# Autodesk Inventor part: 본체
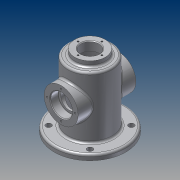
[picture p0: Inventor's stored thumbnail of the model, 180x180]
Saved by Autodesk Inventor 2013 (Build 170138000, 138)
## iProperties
Created: 2014-12
Part Number: 본체
Material: 알루미늄 6061
Document SubType Name: Modeling
Designer: CAD-B13
Mass: 479.555 g
Surface Area: 607.361 cm^2
Volume: 176.958 cm^3
Density: 2.71 g/cm^3
Author: CAD-B13
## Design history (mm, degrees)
sketch "스케치1"
  geometry: L1 (0, 106)-(0, 0); L2 (0, 106)-(22.5, 106); L3 (22.5, 106)-(22.5, 98); L4 (22.5, 98)-(32.5, 98); L5 (32.5, 98)-(32.5, 8); L6 (32.5, 8)-(52.5, 8); L7 (52.5, 8)-(52.5, 0); L8 (52.5, 0)-(0, 0); L9 (13.5, 106)-(13.5, 93); L10 (13.5, 93)-(27.5, 93); L11 (27.5, 93)-(27.5, 0); 1 further point
  constraints: 22 end point, 5 parallel, 5 perpendicular, 2 point on line, 1 coincident, 1 vertical
  dimensions: "d0" = 106 distance of L1.start L1.end; "d2" = 8 distance between parallel lines of L8 L6; "d3" = 45 diameter of L3 L1; "d4" = 65 diameter of L5 L1; "d5" = 98 distance between parallel lines of L8 L4; "d6" = 105 diameter of L7 L1; "d7" = 27 diameter of L9 L1; "d8" = 55 diameter of L11 L1; "d9" = 93 distance between parallel lines of L8 L10
revolve "회전1" sketch "스케치1" stored, may be unused: angle "d10" = 90 deg
node "작업 평면1"
sketch "스케치2"
  geometry: L1 (0, 52.5)-(0, -52.5) reference; C1 r 25 at (55, 0); 2 further points
  constraints: 1 centre point, 1 horizontal alignment, 1 midpoint
  dimensions: "d12" = 55 distance from line of L1 C1.centre; "d13" = 50 diameter of C1
extrude "돌출1" join sketch "스케치2" stored distance "d14" = 10; taper "d15" = 0 deg
hole "구멍1" diameter "d18" = 25; stored, may be unused: countersink angle "d22" = 90 deg, drill point angle "d24" = 0 deg; dims "d16" = 10, "d17" = 10, "d19" = 6, "d20" = 32, "d21" = 12, "d23" = 30.25
sketch "스케치3"
  geometry: C1 r 12.5 at (0, 0) reference; 2 further points
  constraints: 1 vertical alignment
  dimensions: "d25" = 20.5 distance of C1.centre point (0, 20.5)
hole "구멍2" sketch "스케치3" at (0, 20.5) diameter "d26" = 2.459; stored, may be unused: countersink angle "d30" = 90 deg, drill point angle "d32" = 118 deg; dims "d27" = 6, "d28" = 32, "d29" = 12, "d31" = 8
sketch "스케치4" dims "d36" = 86
  geometry: L1 (0, 0)-(30.406, 30.406); L2 (0, 0)-(43, 0); 2 further points
  constraints: 4 end point, 2 coincident, 1 equal length, 1 horizontal, 3 other
  dimensions: "d37" = 45 deg angle of L2 L1
hole "구멍3" sketch "스케치4" at (30.406, 30.406) diameter "d38" = 8; stored, may be unused: countersink angle "d42" = 90 deg, drill point angle "d44" = 0 deg; dims "d39" = 6, "d40" = 32, "d41" = 12, "d43" = 8
sketch "스케치5" dims "d48" = 35
  geometry: 3 further points
  constraints: 2 vertical alignment, 1 coincident, 2 other
hole "구멍4" sketch "스케치5" at (0, 17.5) diameter "d49" = 2.459; stored, may be unused: countersink angle "d53" = 90 deg, drill point angle "d55" = 118 deg; dims "d50" = 6, "d51" = 32, "d52" = 12, "d54" = 8
fillet "모깎기1" dims "d59" = 3
fillet "모깎기2" dims "d60" = 3
chamfer "모따기1" distance "d61" = 1; stored, may be unused: second distance "d62" = 2, angle "d63" = 45 deg
fillet "모깎기3" dims "d64" = 0.3
node "작업 평면2"
node "작업 평면3"
sketch "스케치6"
  geometry: L1 (53, 22.5)-(53, -22.5) reference; L2 (45, 29.5)-(45, -29.5) reference; 3 further points
  constraints: 1 horizontal alignment, 1 midpoint, 1 other
  dimensions: "d65" = 9 distance from line of L2 point (36, 0)
feature "엠보싱1" sketch "스케치6" dims "d66" = 1, "d67" = 0
node "솔리드1"
pattern_circular "원형 패턴1" dims angle "d34" = 360 deg
mirror "대칭1"
pattern_circular "원형 패턴2" dims angle "d46" = 360 deg
pattern_circular "원형 패턴3" dims angle "d57" = 360 deg
other parameters: "d11" = 42.5
